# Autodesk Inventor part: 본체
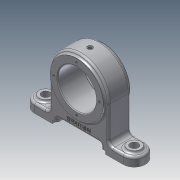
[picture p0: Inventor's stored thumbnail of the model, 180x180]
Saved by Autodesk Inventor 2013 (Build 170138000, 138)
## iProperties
Created: 2019-05
Part Number: 본체
Material: 알루미늄 6061
Document SubType Name: Modeling
Designer: user
Density: 2.71 g/cm^3
Mass: 456.7 g
Surface Area: 318.724 cm^2
Volume: 168.524 cm^3
Author: user
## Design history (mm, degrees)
sketch "스케치1"
  geometry: L1 (40, 0)-(40, -60); L2 (-40, 0)-(-40, -60); L3 (-40, -60)-(40, -60); A1 r 40 centre (0, 0) between (40, 0) and (-40, 0); 1 further point
  constraints: 6 end point, 2 point on circle, 2 tangent, 1 centre point, 1 coincident, 1 parallel
  dimensions: "d0" = 80 diameter of A1; "d2" = 60 distance of L1.start L1.end; "d3" = 60 distance of L2.start L2.end
extrude "돌출1" new body sketch "스케치1" stored distance "d4" = 30; taper "d5" = 0 deg
node "작업 평면1"
sketch "스케치2"
  geometry: L1 (60, -15)-(-60, -15); L2 (-60, 15)-(60, 15); L3 (-60, -15)-(60, -15); L4 (60, -15)-(60, 15); L5 (60, 15)-(-60, 15); L6 (-60, 15)-(-60, -15); L7 (-60, -15)-(60, 15); L8 (60, -15)-(-60, 15); L9 (-60, 15)-(-60, -15); L10 (60, 15)-(60, -15); L11 (0, 15)-(0, -15); C1 r 15 at (-60, 0); 2 further points
  constraints: 22 end point, 5 equal length, 5 midpoint, 2 horizontal, 1 centre point, 1 perpendicular, 1 symmetric about line, 1 vertical alignment, 3 other
  dimensions: "d9" = 120 distance of L2.start L2.end; "d10" = 30 distance of L1.start L2.end
extrude "돌출2" join sketch "스케치2" distance "d11" = 12; taper "d12" = 0 deg
sketch "스케치3"
  geometry: C1 r 36 at (0, 0); A1 r 40 centre (0, 0) between (40, 0) and (-40, 0) reference
  constraints: 1 centre point, 1 coincident
  dimensions: "d13" = 72 diameter of C1
extrude "돌출3" join sketch "스케치3" distance "d14" = 3; taper "d15" = 0 deg
sketch "스케치4"
  geometry: C1 r 36 at (0, 0); A1 r 40 centre (0, 0) between (40, 0) and (-40, 0) reference
  constraints: 1 centre point, 1 coincident
  dimensions: "d16" = 72 diameter of C1
extrude "돌출4" join sketch "스케치4" distance "d17" = 3; taper "d18" = 0 deg
sketch "스케치5"
  geometry: C1 r 36 at (0, 0) reference; C2 r 26 at (0, 0)
  constraints: 1 centre point, 1 coincident
  dimensions: "d19" = 52 diameter of C2
extrude "돌출5" cut sketch "스케치5" stored distance "d20" = 3; taper "d21" = 0 deg
sketch "스케치6"
  geometry: L1 (-40, 0)-(-40, -48) reference; L2 (-60, -60)-(60, -60) reference; L3 (0, -60)-(-36, -60); L4 (-36, -60)-(-36, -56); L5 (-36, -56)-(-30, -56); L6 (-30, -56)-(-30, -50); L7 (-30, -50)-(0, -50); L8 (0, -60)-(0, -50); L9 (30, -50)-(0, -50); L10 (30, -56)-(30, -50); L11 (36, -56)-(30, -56); L12 (36, -60)-(36, -56); L13 (0, -60)-(36, -60)
  constraints: 22 end point, 4 symmetric about line, 3 perpendicular, 1 midpoint, 1 parallel, 1 point on line
  dimensions: "d23" = 36 distance of L3.start L3.end; "d24" = 4 distance of L3.end L4.end; "d26" = 6 distance of L4.end L5.end; "d27" = 6 distance of L5.end L6.end; "d28" = 30 distance of L6.end L7.end
extrude "돌출6" cut sketch "스케치6" stored distance "d29" = 3; taper "d30" = 0 deg
chamfer "모따기1" distance "d31" = 1; stored, may be unused: second distance "d32" = 2, angle "d33" = 45 deg
sketch "스케치8"
  geometry: L1 (0, 27)-(0, 26); C1 r 36 at (0, 0) reference; C2 r 1.5 at (0, 26); 2 further points
  constraints: 3 vertical alignment, 2 end point, 1 centre point, 1 coincident, 1 vertical, 2 other
  dimensions: "d35" = 3 diameter of C2
extrude "돌출7" cut sketch "스케치8" stored distance "d36" = 3; taper "d37" = 0 deg
sketch "스케치9"
  geometry: L1 (0, 0)-(0, 31); C1 r 36 at (0, 0) reference; 1 further point
  constraints: 2 end point, 1 coincident, 1 vertical
  dimensions: "d38" = 31 distance of L1.start L1.end
hole "구멍1" sketch "스케치9" at (0, 31) diameter "d39" = 3.242; stored, may be unused: countersink angle "d43" = 90 deg, drill point angle "d45" = 118 deg; dims "d40" = 6, "d41" = 7, "d42" = 1, "d44" = 8
sketch "스케치10"
  geometry: L1 (60, 15)-(40, 15) reference; L2 (40, -15)-(60, -15) reference; C1 r 9 at (-60, 0); C2 r 9 at (60, 0); A1 r 15 centre (-60, 0) between (-60, 15) and (-60, -15) reference; A2 r 15 centre (60, 0) between (60, -15) and (60, 15) reference; 1 further point
  constraints: 2 centre point, 2 coincident
  dimensions: "d49" = 18 diameter of C1; "d50" = 18 diameter of C2
extrude "돌출8" join sketch "스케치10" distance "d51" = 3; taper "d52" = 0 deg
sketch "스케치11"
  geometry: C1 r 9 at (0, 0) reference; C2 r 9 at (-120, 0) reference; C3 r 5.5 at (-120, 0); C4 r 5.5 at (0, 0); 1 further point
  constraints: 2 centre point, 2 coincident
  dimensions: "d53" = 11 diameter of C3; "d54" = 11 diameter of C4
extrude "돌출9" cut sketch "스케치11" stored distance "d55" = 3; taper "d56" = 0 deg
node "작업 평면2"
sketch "스케치13"
  geometry: 2 further points
  constraints: 1 coincident
hole "구멍3" sketch "스케치13" diameter "d65" = 4.917; stored, may be unused: countersink angle "d69" = 90 deg, drill point angle "d71" = 0 deg; dims "d66" = 8, "d67" = 7, "d68" = 1, "d70" = 10
fillet "모깎기1" dims "d77" = 6
fillet "모깎기2" dims "d78" = 3
fillet "모깎기3" dims "d79" = 3
fillet "모깎기4" dims "d80" = 3
fillet "모깎기5" dims "d81" = 3
sketch "스케치18"
  geometry: L1 (-27, -50)-(27, -50) reference; C1 r 36 at (0, 0) reference; 1 further point
  constraints: 1 vertical alignment, 1 other
  dimensions: "d82" = 7 distance from line of L1 point (0, -43)
feature "엠보싱1" sketch "스케치18" dims "d0" = 80, "d2" = 60, "d3" = 60, "d83" = 0.5, "d84" = 0
fillet "모깎기6" dims "d92" = 3
fillet "모깎기7" dims "d93" = 3
sketch "스케치21"
  geometry: C1 r 2.458 at (0, 0) reference; 1 further point
  constraints: 1 coincident
hole "구멍4" sketch "스케치21" at (0, 0) diameter "d94" = 2; stored, may be unused: countersink angle "d98" = 90 deg, drill point angle "d100" = 0 deg; dims "d95" = 6, "d96" = 5, "d97" = 2, "d99" = 8
node "솔리드1"
pattern_circular "원형 패턴1" dims angle "d47" = 360 deg
mirror "대칭1"
